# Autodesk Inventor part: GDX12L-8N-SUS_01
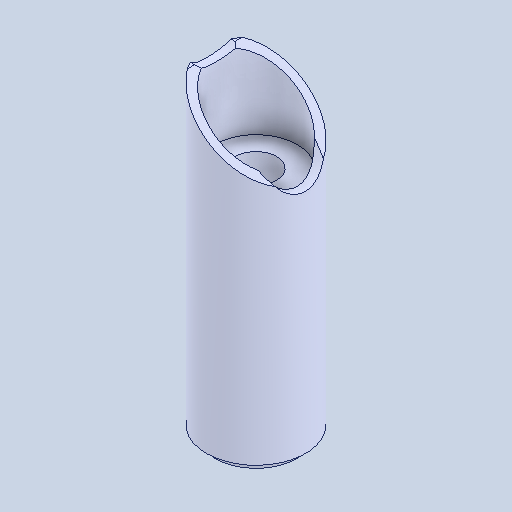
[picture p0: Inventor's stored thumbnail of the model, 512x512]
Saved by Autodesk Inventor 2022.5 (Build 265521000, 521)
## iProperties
Created: 2024-06
Part Number: GDX12L-8N-SUS_01
Material: 一般
Document SubType Name: Modeling
Designer: ImaoCorp
Density: 1 g/cm^3
Appearance: 既定
Author: ImaoCorp
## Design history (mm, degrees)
feature "GDX12L-8N-SUS_01"
node "ソリッド1"
